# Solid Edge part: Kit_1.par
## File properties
Sűrűség: 0,000 kg/m^3
Pontosság: 0,990
Author: ahadarics
Last saved by: ahadarics
Revision: 77
Username: ahadarics
Dokumentum tartalom típus: 0
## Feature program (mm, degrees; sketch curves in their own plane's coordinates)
base feature "unnamed BaseFeature 1"
thread "unnamed Thread 1"
chamfer "unnamed Chamfer 1"
sketch for "Furat_1" plane through (0, -45, 8.5) normal (0, 0, 1) x-axis (0, 1, 0)
  hole centre (0, 0) bore radius 2.067
hole "Furat_1" nominal diameter 5 finite  ThreadDepth = 4.5 mm
chamfer "Letörés_2" setback 0.5
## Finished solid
Body 1: solid body, 94 faces, 164 edges, 72 vertices, 2 internal voids.
  Faces by surface: plane 42, cylinder 18, cone 17, torus 17
  Edges by curve: circle 73, line 42, spline 36, intersection 13
Bounding box of the edges (mm; curved faces can reach further): 19.000 x 34.000 x 18.100, from (-9.5, -67.5, -9.5) to (9.5, -33.5, 8.6).
Cylindrical faces by radius (mm): R2.06 x1, R2.067 x1, R3 x1, R3.25 x1, R3.55 x1, R4.5 x2, R4.55 x1, R4.75 x1, R5.55 x1, R5.6 x1, R6.85 x1, R7.25 x1, R8 x3, R8.6 x1, R9.5 x1
Conical faces (half-angle, radius in mm at the cone's reference point): 8.8315 deg R4.75 x1, 15 deg R5.55 x1, 20.542 deg R3.55 x1, 27.3182 deg R3.0335 x1, 29.1112 deg R4.1553 x1, 30 deg R7.9134 x1, 45 deg R2.567 x1, 45 deg R3.05 x2, 45 deg R3.35 x1, 45 deg R4.45 x2, 45 deg R4.65 x1, 45 deg R4.8 x1, 45 deg R7.625 x1, 45 deg R8 x1, 60 deg R7.425 x1
Toroidal faces (ring radius, tube radius in mm): R3.3 r0.3 x12, R4.3301 r0.2 x1, R4.35 r0.2 x1, R5.35 r0.2 x1, R5.4 r0.2 x2
Planar faces by outward normal: +x 3, +y 14, +z 2, -x 3, -y 8, oblique 12
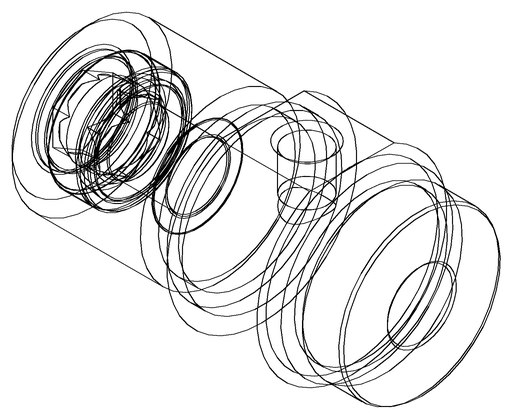
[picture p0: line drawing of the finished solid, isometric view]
